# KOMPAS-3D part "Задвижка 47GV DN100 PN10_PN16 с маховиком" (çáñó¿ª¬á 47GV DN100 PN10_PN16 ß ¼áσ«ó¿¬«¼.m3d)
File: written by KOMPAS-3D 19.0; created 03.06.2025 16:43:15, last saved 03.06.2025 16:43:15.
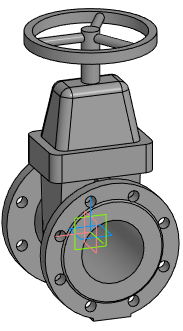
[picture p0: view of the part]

Document properties: Автор: Евгений; Полное имя файла: E:\Dendor Работа Сачек\3D для проекитирвщиков\2.1 Тип 47GV, 47GV.Z Задвижка клиновая фланцевая с обрезиненным клином\stp_Тип 47GV. Задвижка DN40-DN350 с маховиком\Задвижка 47GV DN100 PN10_PN16 с маховиком.m3d

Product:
- Part/product: Задвижка 47GV DN100 PN10_PN16 с маховиком

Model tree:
1. Операция без истории:1  (labels: Задвижка 47GV DN100 PN10_PN16 с маховиком)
